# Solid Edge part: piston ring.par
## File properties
Author: Deepak Maini
Template: Normal.par
Last saved by: Robert a Rhodes jr
Revision: 4
Application: Solid Edge
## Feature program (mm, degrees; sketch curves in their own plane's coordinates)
sketch for "unnamed Protrusion 1" #1 plane through (0, 0, 0) normal (0, 0, 1) x-axis (1, 0, 0)
  circle centre (0, 0) radius 42.5
sketch for "unnamed Protrusion 1" #2 plane through (0, 0, 0) normal (0, 0, 1) x-axis (1, 0, 0)
  circle centre (0, 0) radius 46.5
extrude "unnamed Protrusion 1" add finite 3 along -normal
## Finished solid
Body 1: solid body, 4 faces, 4 edges, 0 vertices.
  Faces by surface: cylinder 2, plane 2
  Edges by curve: circle 4
Bounding box of the edges (mm): 93.000 x 93.000 x 3.000, from (-46.5, -46.5, -3) to (46.5, 46.5, 0).
Cylindrical faces by radius (mm): R42.5 x1, R46.5 x1
Planar faces by outward normal: +z 1, -z 1
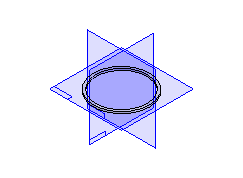
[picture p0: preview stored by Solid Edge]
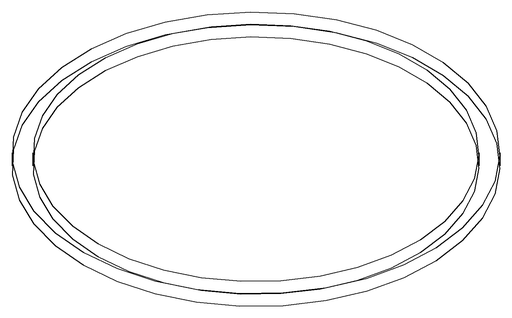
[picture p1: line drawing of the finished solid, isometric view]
